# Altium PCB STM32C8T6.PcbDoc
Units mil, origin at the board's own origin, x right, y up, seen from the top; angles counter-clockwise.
Board outline 3865.24 x 3866.42 mil, 2 copper layers (Top Layer, Bottom Layer); 70 components, 62 nets, 378 pads, 47 vias.
Unrouted connection lines stored in the file: 3.
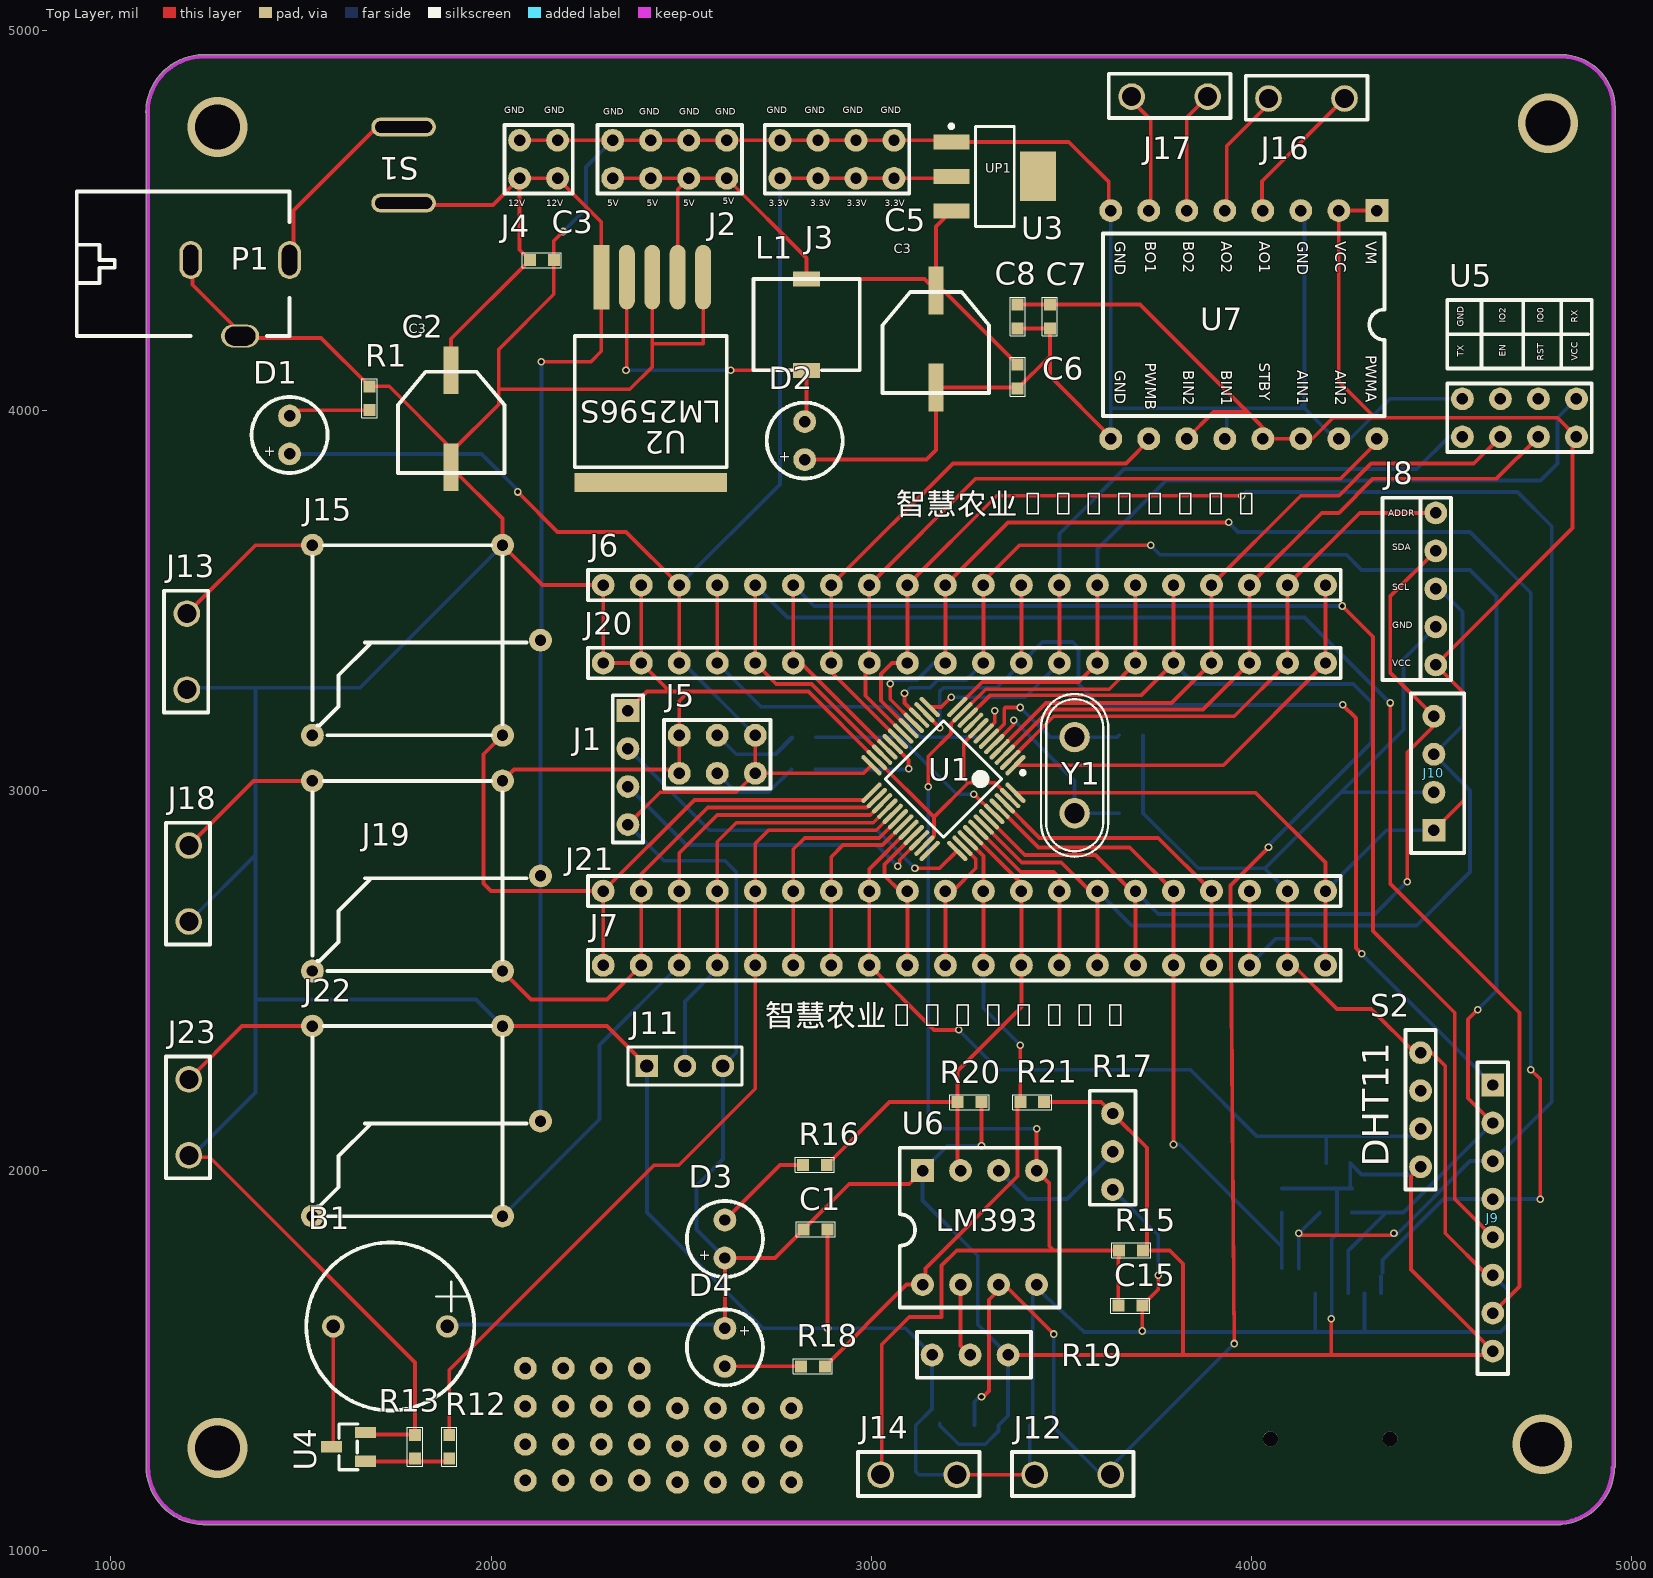
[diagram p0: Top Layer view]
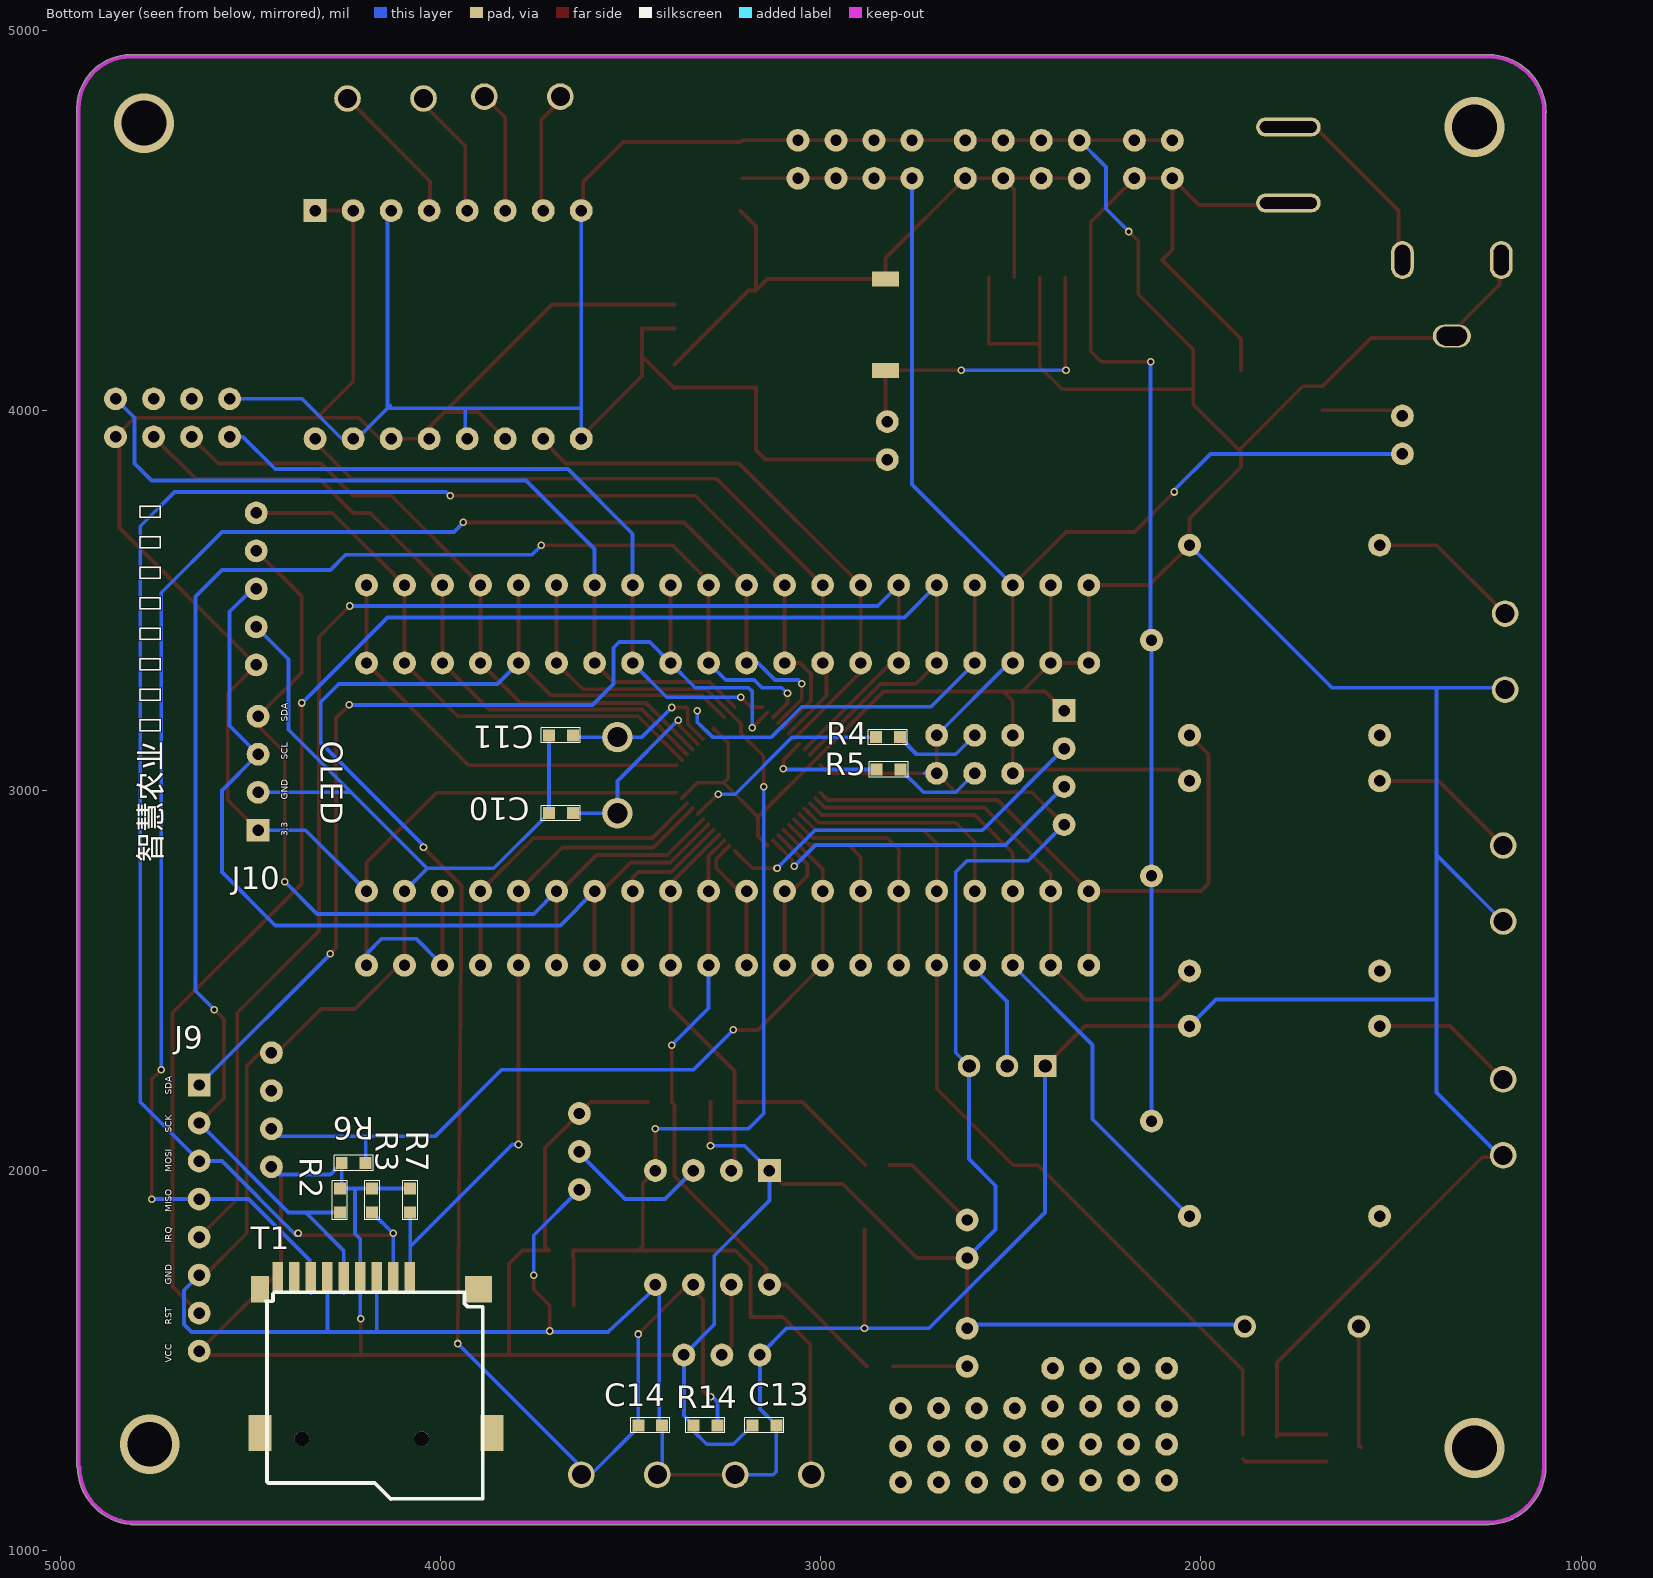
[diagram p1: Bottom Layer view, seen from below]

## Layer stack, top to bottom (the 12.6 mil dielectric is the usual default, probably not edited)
Top Solder: solder mask 0.4, Solder Resist, Dk 3.5
Top Layer: signal copper 1.4
Dielectric 1: dielectric 12.6, FR-4, Dk 4.8
Bottom Layer: signal copper 1.4
Bottom Solder: solder mask 0.4, Solder Resist, Dk 3.5

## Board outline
1093.29,1209.33 cw(c1098.09,1210.79) 1093.07,1210.79 1093.07,1212.39 cw(c1245.5,1221.67) 1092.81,1219.39 cw(c1097.82,1219.47) 1093.07,1221.08 1093.07,4781.92 cw(c1097.01,4785.02) 1092,4785.1 cw(c1244.68,4782.52) 1093.07,4800.77 1093.07,4801.91 cw(c1098.09,4801.91) 1093.48,4803.9 cw(c1244.68,4782.52) 1242.41,4935.21 cw(c1242.48,4930.2) 1243.37,4935.13 4814.56,4935.13 cw(c4814.56,4930.12) 4815.76,4934.98 cw(c4816.88,4930.1) 4816.97,4935.11 cw(c4814.56,4792.6) 4957.05,4795.95 cw(c4952.22,4794.6) 4957.24,4794.6 4957.24,1222.21 cw(c4952.22,1222.21) 4954.98,1218.02 cw(c4802.32,1221.48) 4815.96,1069.38 cw(c4814,1074) 4814,1068.98 4810.37,1068.98 cw(c4802.32,1221.48) 4804.59,1068.79 cw(c4804.52,1073.8) 4803.13,1068.98 1242,1068.98 cw(c1242,1074) 1241.42,1069.02 cw(c1245.5,1221.67)

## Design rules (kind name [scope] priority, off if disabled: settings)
Clearance [All] p1: gap=5
DiffPairsRouting [All] p1: maxlimit=5 minlimit=2 mostfreqgap=2 toplayer_minwidth=1 toplayer_maxwidth=5 toplayer_prefwidth=3 bottomlayer_minwidth=1 bottomlayer_maxwidth=5 bottomlayer_prefwidth=3 maxuncoupledlength=500
PolygonConnect [All] p1: connectstyle=Relief reliefconductorwidth=10 reliefentries=4 polygonreliefangle="90 Angle" airgapwidth=10
RoutingVias [All] p1: holewidth=5 width=10 viastyle="Through Hole" minholewidth=3 minwidth=5 maxholewidth=8 maxwidth=15
SolderMaskExpansion [All] p1: expansion=4
Width [All] p1: maxlimit=12 minlimit=5 preferedwidth=10 minimp=50.000000 maximp=50.000000 favimp=50.000000
28 further rules are at their usual default settings.

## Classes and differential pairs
component class Sheet2: C13 C14 C15 D3 D4 J8 J9 J10 J11 J12 J13 J14 J15 J16 J17 J18 J19 J22 J23 R14 R15 R16 R17 R18 R19 R20 R21 U5 U6 U7
component class Sheet1: B1 C1 C2 C3 C5 C6 C7 C8 C10 C11 D1 D2 J1 J2 J3 J4 J5 J6 J7 J20 J21 L1 P1 R1 R2 R3 R4 R5 R6 R7 R12 R13 S1 S2 T1 U1 U2 U3 U4 Y1

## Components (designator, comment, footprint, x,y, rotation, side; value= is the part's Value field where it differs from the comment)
B1 "BEEP" BEEP-9.5X5.5 1785,1590 r180 top
C1 "104" CAP_0603_FIRE 2885,1845 r180 top
C2 "220UF35V" CAP+_47UF_FIRE 1895,3995 r0 top
C3 "0.1UF" CAP_0603_FIRE 2165,4395 r180 top
C5 "220UF35V" CAP+_47UF_FIRE 3170,4205 r0 top
C6 "0.1UF" CAP_0603_FIRE 3385,4120 r270 top
C7 "22UF" CAP_0603_FIRE 3470,4215 r90 top
C8 "0.1UF" CAP_0603_FIRE 3385,4215 r90 top
C10 "20P" CAP_0603_FIRE 3715,2940 r180 bottom
C11 "20P" CAP_0603_FIRE 3715,3145 r180 bottom
C13 "104" CAP_0603_FIRE 3180,1330 r180 bottom
C14 "104" CAP_0603_FIRE 3417.01,1330 r0 bottom
C15 "104" CAP_0603_FIRE 3650,1645 r0 top
D1 "LED" LED_Z 1470,3885 r90 top
D2 "ES2D" LED_Z 2825,3870 r90 top
D3 "LED" LED_Z 2615,1770 r90 top
D4 "LED" LED_Z 2615,1585 r270 top
J1 "SWD" SWD 2360,3210 r0 top
J2 "5V" 5V 2320,4610 r90 top
J3 "3.3V" 3.3V 2760,4610 r90 top
J4 "12V" 12V 2075,4610 r90 top
J5 "BOOT" BOOT 2695,3145 r270 top
J6 "Hander_20" Hander_20 4195,3540 r270 top
J7 "Hander_20" Hander_20 4195,2540 r270 top
J8 "GY-302" GY 4485,3330 r180 top
J9 "RFID" RFID 4635,2225 r270 top
J10 "OLED" OLED 4480,2895 r90 top
J11 "HC-SR501" HDR1X3 2410,2275 r0 top
J12 "K1" port_2 3630,1200 r180 top
J13 "电磁阀" port_2 1200,3465 r270 top
J14 "Port" port_2 3225,1200 r180 top
J15 "relay" relay 1530,3145 r90 top
J16 "电机" port_2 4245,4820 r180 top
J17 "电机" port_2 3885,4825 r180 top
J18 "电磁阀" port_2 1205,2855 r270 top
J19 "relay" relay 1530,2525 r90 top
J20 "Hander_20" Hander_20 4195,3335 r270 top
J21 "Hander_20" Hander_20 4195,2735 r270 top
J22 "relay" relay 1530,1880 r90 top
J23 "电磁阀" port_2 1205,2240 r270 top
L1 "L" L 2830,4105 r180 top
P1 "Power" POWER 1310,4195 r90 top
R1 "1.5K" R_0603 1680,4000 r90 top
R2 "47K" R_0603 4265,1890 r90 bottom
R3 "47K" R_0603 4180,1890 r90 bottom
R4 "10K" R_0603 2855,3140 r180 bottom
R5 "10K" R_0603 2790,3055 r0 bottom
R6 "RES" R_0603 4260,2020 r180 bottom
R7 "47K" R_0603 4080,1890 r90 bottom
R12 "1K" R_0603 1890,1305 r270 top
R13 "10K" R_0603 1800,1305 r270 top
R14 "10K" R_0603 3272,1330 r0 bottom
R15 "10K" R_0603 3715,1790 r180 top
R16 "1k" R_0603 2820,2015 r0 top
R17 "103" RES_R 3635,1950 r180 top
R18 "1k" R_0603 2815,1485 r0 top
R19 "103" RES_R 3160,1515 r90 top
R20 "10K" R_0603 3290,2180 r180 top
R21 "10K" R_0603 3455,2180 r180 top
S1 "" SWITCH 1770,4745 r270 top
S2 "DHT11" DHT11 4445,2010 r90 top
T1 "TF" TF_CARD 4475,1310 r180 bottom
U1 "stm32c8t6" LQFP48_N 3190,3030 r225 top
U2 "LM2596" LM2596 2290,4350 r90 top
U3 "AMS1117" AMS-1117-3.3 3325,4615 r0 top
U4 "9014" SOT-23 1670,1235 r90 top
U5 "ESP8266" ESP8266 4555,3930 r90 top
U6 "LM393" LM393 3135,1700 r90 top
U7 "TB6612" TB6612 4330,4525 r270 top
Y1 "8MHZ" XTAL_socket 3535,3040 r90 top

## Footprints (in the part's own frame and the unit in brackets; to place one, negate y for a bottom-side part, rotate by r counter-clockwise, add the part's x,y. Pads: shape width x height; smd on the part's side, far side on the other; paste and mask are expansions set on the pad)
3.3V [mil]
  round 60 hole 30: 1(0,0) 2(0,-100) 3(0,-200) 4(0,-300) 5(100,-300) 6(100,-200) 7(100,-100) 8(100,0)
  silkscreen extent -40,-340 140,40
5V [mil]
  round 60 hole 30: 1(0,0) 2(0,-100) 3(0,-200) 4(0,-300) 5(100,0) 6(100,-100) 7(100,-200) 8(100,-300)
  silkscreen extent -40,-340 140,40
12V [mil]
  round 60 hole 30: 1(0,0) 2(0,-100) 3(100,0) 4(100,-100)
  silkscreen extent -40,-140 140,40
AMS-1117-3.3 [mm]
  rect 2.4x1 smd: 1(-2.9,2.3) 2(-2.9,0) 3(-2.9,-2.3)
  rect 2.4x3.3 smd: 4(2.9,0)
  silkscreen extent -3.02,-3.35 1.3,3.47
BEEP-9.5X5.5 [mm]
  round 1.5 hole 0.9: 1(-2.54,0) 2(5.08,0)
  silkscreen extent -4.34,-5.61 6.88,5.61
BOOT [mil]
  round 60 hole 30: 1(0,0) 2(0,-100) 3(0,-200) 4(100,-200) 5(100,-100) 6(100,0)
  silkscreen extent -40,-240 140,40
CAP+_47UF_FIRE [mm]
  rect 1x3.2 smd: 1(0,2.8) 2(0,-3.683)
  silkscreen extent -3.56,-4.06 3.56,2.7
CAP_0603_FIRE [mm]
  rect 0.8x0.8 smd: 1(0,0) 2(1.6,0)
  silkscreen extent -0.5,-0.5 2.1,0.5
DHT11 [mil]
  round 60 hole 30: 1(0,0) 2(100,0) 3(200,0) 4(300,0)
  silkscreen extent -60,-40 360,40
ESP8266 [mil]
  round 60 hole 30: 1(0,-300) 2(0,-200) 3(0,-100) 4(0,0) 5(100,-300) 6(100,-200) 7(100,-100) 8(100,0)
  silkscreen extent -40,-340 360,40
GY [mil]
  round 60 hole 30: 1(0,0) 2(0,-100) 3(0,-200) 4(0,-300) 5(0,-400)
  silkscreen extent -40,-440 140,40
Hander_20 [mil]
  round 60 hole 30: 1(0,0) 2(0,-100) 3(0,-200) 4(0,-300) 5(0,-400) 6(0,-500) 7(0,-600) 8(0,-700) 9(0,-800) 10(0,-900) 11(0,-1000) 12(0,-1100) 13(0,-1200) 14(0,-1300) 15(0,-1400) 16(0,-1500) 17(0,-1600) 18(0,-1700) 19(0,-1800) 20(0,-1900)
  silkscreen extent -40,-1940 40,40
HDR1X3 [mm] "Connector; Header; 3 Position"
  rect 1.5x1.5 hole 0.9: 1(0,0)
  round 1.5 hole 0.9: 2(2.54,0) 3(5.08,0)
  silkscreen extent -1.27,-1.27 6.35,1.27
L [mm]
  rect 1.8x1 all layers, no hole: 1(0,0) 2(0,-6.096)
  silkscreen extent -3.56,-6.1 3.56,0
LED_Z [mil]
  round 60 hole 30: 1(0,0) 2(100,0)
  silkscreen extent -50,-100 150,100
LM393 [mil]
  round 60 hole 30: 1(0,0) 2(0,-100) 3(0,-200) 4(0,-300) 5(300,-300) 6(300,-200) 7(300,-100)
  rect 60x60 hole 30: 8(300,0)
  silkscreen extent -60,-360 360,60
LM2596 [mil]
  rect 170x42 smd: 1(0,0)
  oval 170x42 smd: 2(0,-67) 3(0,-134) 4(0,-201) 5(0,-268)
  rect 50x400 smd: 6(-540,-130)
  silkscreen extent -500,-330 -155,70
LQFP48_N [mm]
  oval 1.8x0.3 smd: 1(-4.05,2.75) 2(-4.05,2.25) 3(-4.05,1.75) 4(-4.05,1.25) 5(-4.05,0.75) 6(-4.05,0.25) 7(-4.05,-0.25) 8(-4.05,-0.75) 9(-4.05,-1.25) 10(-4.05,-1.75) 11(-4.05,-2.25) 12(-4.05,-2.75) 25(4.05,-2.75) 26(4.05,-2.25) 27(4.05,-1.75) 28(4.05,-1.25) 29(4.05,-0.75) 30(4.05,-0.25) 31(4.05,0.25) 32(4.05,0.75) 33(4.05,1.25) 34(4.05,1.75) 35(4.05,2.25) 36(4.05,2.75)
  oval 0.3x1.8 smd: 13(-2.75,-4.05) 14(-2.25,-4.05) 15(-1.75,-4.05) 16(-1.25,-4.05) 17(-0.75,-4.05) 18(-0.25,-4.05) 19(0.25,-4.05) 20(0.75,-4.05) 21(1.25,-4.05) 22(1.75,-4.05) 23(2.25,-4.05) 24(2.75,-4.05) 37(2.75,4.05) 38(2.25,4.05) 39(1.75,4.05) 40(1.25,4.05) 41(0.75,4.05) 42(0.25,4.05) 43(-0.25,4.05) 44(-0.75,4.05) 45(-1.25,4.05) 46(-1.75,4.05) 47(-2.25,4.05) 48(-2.75,4.05)
  silkscreen extent -4.17,-2.75 2.75,3.57
OLED [mil]
  rect 60x60 hole 30: 1(0,0)
  round 60 hole 30: 2(100,0) 3(200,0) 4(300,0)
  silkscreen extent -60,-80 360,60
port_2 [mil]
  round 70 hole 50: 1(0,0) 2(200,0)
  silkscreen extent -60,-60 260,56
POWER [mil]
  oval 100x60 hole 40 slot 80 at 0 deg: 1(200,100) 3(200,-160)
  oval 60x100 hole 50 slot 80 at 90 deg: 2(0,-30)
  silkscreen extent 0,-160 380,400
R_0603 [mm]
  rect 0.8x0.8 smd: 1(0,0) 2(1.6,0)
  silkscreen extent -0.51,-0.51 2.11,0.51
relay [mil]
  round 60 hole 30: 1(0,0) 2(0,-500) 3(250,-600) 4(500,-500) 5(500,0)
  silkscreen extent 0,-564 500,0
RES_R [mil]
  round 60 hole 30: 1(0,0) 2(0,-200) 3(0,-100)
  silkscreen extent -60,-260 60,40
RFID [mil]
  rect 60x60 hole 30: 1(0,0)
  round 60 hole 30: 2(100,0) 3(200,0) 4(300,0) 5(400,0) 6(500,0) 7(600,0) 8(700,0)
  silkscreen extent -60,-40 760,40
SOT-23 [mil]
  rect 30x55 smd: 1(0,0) 2(76,0) 3(38,90)
  silkscreen extent -22,20 98,70
SWD [mil]
  rect 60x60 hole 30: 1(0,0)
  round 60 hole 30: 2(0,-100) 3(0,-200) 4(0,-300)
  silkscreen extent -40,-347 40,40
SWITCH [mil]
  oval 50x170 hole 30 slot 150 at 90 deg: 1(0,0) 2(200,0)
TB6612 [mil]
  rect 60x60 hole 30: 1(0,0)
  round 60 hole 30: 2(0,-100) 3(0,-200) 4(0,-300) 5(0,-400) 6(0,-500) 7(0,-600) 8(0,-700) 9(600,0) 10(600,-100) 11(600,-200) 12(600,-300) 13(600,-400) 14(600,-500) 15(600,-600) 16(600,-700)
  silkscreen extent 60,-720 540,20
TF_CARD [mm]
  rect 0.7x2.1 smd: 1(10,10.35) 2(8.9,10.35) 3(7.8,10.35) 4(6.7,10.35) 5(5.6,10.35) 6(4.5,10.35) 7(3.4,10.35) 8(2.3,10.35) 9(1.2,10.35)
  rect 1.2x1.778 smd: 10(0,9.6)
  rect 1.524x2.413 smd: 11(0,0) 12(15.5,0)
  rrect0% 1.778x1.778 smd: 13(14.6,9.6)
  round 1 hole 1: 14(10.8,-0.4) 15(2.8,-0.4)
  silkscreen extent 0.41,-4.42 14.88,9.4
XTAL_socket [mil]
  round 80 hole 53: 1(100,0) 2(-100,0)
  silkscreen extent -215,-89 214,89

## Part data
C1 C3 C6 C7 C8 C10 C11 C13 C14 C15: library part Capacitance
C2 C5: library part Capactiance+
D2: library part LED
J12 J13 J16 J17 J18 J23: library part port_2
R1 R2 R3 R4 R5 R7 R12 R13 R14 R15 R16 R18 R20 R21: library part RES
R17 R19: library part RES_R
S1: library part Switch
Y1: library part XTAL

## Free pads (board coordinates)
  round 60 hole 30: 0(2090,1185) 0(2090,1280) 0(2090,1380) 0(2090,1480) 0(2490,1180) 0(2490,1275) 0(2490,1375) 2(2190,1185) 2(2190,1280) 2(2190,1380) 2(2190,1480) 2(2590,1180) 2(2590,1275) 2(2590,1375) 3(2290,1185) 3(2290,1280) 3(2290,1380) 3(2290,1480) 3(2690,1180) 3(2690,1275) 3(2690,1375) 4(2390,1185) 4(2390,1280) 4(2390,1380) 4(2390,1480) 4(2790,1180) 4(2790,1275) 4(2790,1375)

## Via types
v1: diameter 20, hole 12, Top Layer to Bottom Layer, 43 vias
v2: diameter 157.48, hole 118.11, Top Layer to Bottom Layer, 4 vias

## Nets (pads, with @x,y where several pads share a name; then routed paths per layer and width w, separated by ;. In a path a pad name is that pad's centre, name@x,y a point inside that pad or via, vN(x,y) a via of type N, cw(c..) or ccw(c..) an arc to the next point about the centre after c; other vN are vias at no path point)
3.3V: B1.1 C1.2 C7.2 C8.2 C13.1 D1.1 D3.1 D4.1 J1.4 J3.1 J3.2 J3.3 J3.4 J5.1 J5.6 J6.18 J7.1 J7.3 J8.1 J9.8 J10.1 J11.3 J20.18 J21.1 J21.3 R2.2 R3.2 R6.1 R7.2 R14.2 R15.1 R17.2 R19.2 R20.1 R21.1 S2.1 T1.4 U1.9 U1.24 U1.36 U1.48 U3.2 U5.1 U6.8 U7.1 U7.2 U7.11 U7.12 U7.14 | length 17842.1
  Top Layer w10: v1(2070,3785) 2175,3680 2355,3680 J6.18 J20.18 ; J1.4 2445,2995 2645,2995 J5.6 ; D4.1 D3.1 2747.01,1770 C1.2 2942.01,1965 3100,1965 U6.8 ; J5.1 J5.6 ; J3.1 J3.2 J3.3 J3.4 U3.2@3205.83,4610 ; U1.24 2979.51,3045 J5.6 ; v1(3290,2065) R20.1 ; R19.2 3820,1515 ; U1.48 4011.19,2993.81 4195,2810 J21.1 J7.1 ; C8.2 C7.2 3707.01,4277.99 3990,3995 ; R21.1 3605,2180 R17.2 3725,2060 3725,1800 R15.1 3785,1790 3820,1755 3820,1515 ; U7.14 3900,3995 3990,3995 ; J7.3 J21.3 ; 4210,1520 v1(4210,1610) ; U7.1 U7.2 4230,4075 4325,3980 ; S2.1 4420,1985 4420,1740 J9.8 ; J10.1 4560,2975 4560,3255 J8.1 4845,3690 U5.1@4845,3930 ; J9.8@4625,1515 3820,1515 ; U5.1 4805,3980 4325,3980 ; 3990,3995 4060,3925 4160,3925 4215,3980 4325,3980
  Bottom Layer w10: D1.1 1975,3885 2067.5,3792.5 2067.5,3787.5 v1(2070,3785) ; B1.1@1870,1595 2605,1595 D4.1 ; J1.4 2455,2815 2615,2815 2645,2785 2645,2310 J11.3 2610,2030 2540,1960 2540,1845 D3.1 ; J20.18 2505,3335 J5.1 ; J6.18 2760,3805 J3.1@2760,4600 ; J5.6 2728,3045 ; C13.1@3180,1335 C13.1 3230,1280 3300,1280 3334.99,1314.99 R14.2 3360,1355.01 R19.2 3280,1595 3280,1776 3135,1921 U6.8 3200,2065 v1(3290,2065) ; J7.3 4065,2610 4155,2610 4195,2570 J7.1 ; R7.2 R3.2 4225,1952.99 ; J21.1 4355,2895 J10.1 ; v1@4211.22,1606.22 4211.22,1820 4225,1833.78 4225,1952.99 ; R2.2@4260,1957.99 R6.1 4290,1990 4425,1990 S2.1 ; R2.2 4225,1952.99 ; J9.8@4625,1515 J9.8
5V: C5.1 C6.1 J2.1 J2.2 J2.3 J2.4 L1.2 U2.4 U3.3 | length 1798.3
  Top Layer w10: J2.1 J2.2 J2.3 ; U2.4 2491,4581 J2.3 ; U3.3 3170,4483.62 C5.1 ; C6.1 3189.76,4315.24 C5.1 ; J2.3 J2.4 2830,4400 L1.2 3140.24,4345 C5.1
12V: C2.1 C3.2 J4.1 J4.2 J15.3 J19.3 J22.3 S1.2 U2.1 | length 3709.9
  Top Layer w10: S1.2@1770,4530 1780,4540 2005,4540 J4.1 ; C2.1 1895,4187.99 C3.2 2075,4422.01 J4.1 ; v1(2132.5,4127.5) 2262.5,4127.5 2290,4155 U2.1 2290,4495 J4.2 J4.1
  Bottom Layer w10: J22.3 J19.3 J15.3 2132.5,3397.5 v1(2132.5,4127.5)
BEEP: J7.16 J21.16 R12.1 U1.29 | length 2320.3
  Top Layer w10: R12.1 1890,1475 2428.75,2013.75 2493.75,2013.75 2695,2215 J7.16 J21.16 2695,2860 2730,2895 3013.24,2895 U1.29
BOOT0: R4.1 U1.44 | length 551.7
  Top Layer w10: v1(3270,2990) U1.44
  Bottom Layer w10: R4.1 3075,3140 3225,2990 v1(3270,2990)
BOOT1: R5.2 U1.20 | length 328.4
  Top Layer w10: U1.20 3098.24,3080 v1(3098.24,3056.76)
  Bottom Layer w10: R5.2 3096.48,3055 v1(3098.24,3056.76)
FIRE_IN: C15.1 J6.6 J14.2 J20.6 R15.2 U1.11 U6.5 | length 3741.7
  Top Layer w10: J14.2 3027.5,1202.5 3027.5,1542.5 3100,1615 3185,1615 3185,1750 3225,1790 R15.2 3652.01,1770.01 3650,1768 C15.1 ; v1(3150,3010) 3150,3090 3210,3150 3210,3175.27 U1.11 ; U1.11@3240.38,3205.38 3301.22,3266.22 3626.22,3266.22 J20.6 J6.6 ; v1(3435,2110) U6.5 3468,1967 3468,1802 3480,1790
  Bottom Layer w10: v1(3150,3010) 3150,2150 3190,2110 v1(3435,2110)
FIRE_IN2: R17.3 U6.6 | length 385.8
  Bottom Layer w10: U6.6 3410,1925 3515,1925 3635,2045 R17.3
FIRE_OUT: J7.9 J21.9 R16.2 R20.2 U1.40 U6.7 | length 1420.3
  Top Layer w10: R16.2 3047.99,2180 R20.2 ; U6.7 3227.01,2007.99 R20.2 ; U1.40 3395,2755.4 J21.9 J7.9 3395,2430 3227.01,2262.01 R20.2
GND: C1.1 C2.2 C3.1 C5.2 C6.2 C7.1 C8.1 C10.1 C11.1 C13.2 C14.1 C15.2 D2.1 J1.1 J2.5 J2.6 J2.7 J2.8 J3.5 J3.6 J3.7 J3.8 J4.3 J4.4 J5.3 J5.4 J6.19 J6.20 J7.2 J8.2 J9.6 J10.2 J11.1 J12.2 J13.2 J14.1 J15.4 J18.2 J19.4 J20.19 J20.20 J21.2 J22.4 J23.2 P1.1 P1.2 R1.2 R13.1 R17.1 R19.1 S2.4 T1.3 T1.6 U1.8 U1.23 U1.35 U1.47 U2.3 U2.5 U3.1 U4.2 U5.8 U6.4 U7.3 U7.8 U7.10 U7.13 U7.16 | length 24302.7
  Top Layer w10: P1.1@1215,4420 1215,4330 P1.2@1360,4185 ; J23.2@1220,2035 1260,2035 1800,1495 R13.1@1800,1300 ; P1.2@1350,4190 1552.99,4190 R1.2 1732.01,4062.99 C2.2@1895,3900 ; U4.2@1670,1306 R13.1@1800,1306 ; 2025,4055 2365,4055 2424,4114 2424,4175 ; J22.4 2305,2380 J11.1 ; J19.4 2060,3055 2485,3055 J5.4 J5.3 2495,3235 2520,3260 ; J4.3 J4.4 J2.5 J2.6 J2.7 J2.8 J3.8 J3.7 J3.6 J3.5 U3.1@3206.38,4710 ; v1(2190,4470) 2165,4445 C3.1 2165,4305 2020,4160 2020,4015 1895,3890 C2.2 2030,3715 J15.4 2135,3540 J6.20 J20.20 J20.19 ; J1.1 2410,3260 2470,3260 ; J6.19 J20.19 ; U2.3 2424,4175 ; U2.5 2558,4175 2424,4175 ; D2.1 3145,3870 3170,3895 C5.2 3385,4060 C6.2 3470,4142.01 C7.1 ; v1(2885,1585) C1.1 ; U1.35 3165,2879.73 3165,2929.73 ; U3.1 3519.45,4705.55 3625,4600 U7.8@3625,4540 ; J14.1@3212.01,1200 J14.1 J12.2 J12.2@3460,1200 ; U1.8@3281.87,3161.87 U1.8 3243.24,3125 3243.24,3032.03 3255.27,3020 ; U1.47 3325.27,3020 3255.27,3020 ; C8.1 C7.1 ; U7.16@3635,3925 3470,4090 C7.1 ; v1(3712.99,1577.99) C15.2 3755,1687.01 v1(3755,1725) ; J21.2 J7.2 4110,2540 4225,2425 4315,2425 4430,2310 4475,2310 4510,2275 4510,1835 4620,1725 J9.6 ; J20.19 2470,3260 ; 2470,3260 2520,3260 ; 2520,3260 2834.73,3260 U1.23 3165,2929.73 ; 3165,2929.73 3255.27,3020
  Bottom Layer w10: J13.2 1205,3270 1380,3270 ; J23.2@1205,2030 1380,2205 1380,2830 ; J18.2@1212.5,2662.5 1380,2830 ; 1385,2450 1960,2450 J22.4 ; J15.4 1655,3270 1380,3270 ; v1(2190,4470) 2250,4530 2250,4640 J2.5 ; J11.1 2410,1890 2715,1585 v1(2885,1585) 3090,1585 R19.1 3160,1372.99 C13.2 3117.01,1207.99 3125,1200 J14.1 ; J12.2 3417.01,1212.99 C14.1 3425,1337.99 3425,1700 3560,1575 4655,1575 4675,1595 4675,1685 J9.6 ; U7.16 3630,4005 ; U7.8 3630,4005 ; R17.1 3755,1830 v1(3755,1725) ; C11.1 C10.1 3860,2795 4035,2795 4035.27,2794.73 J21.2 ; U7.13@3935,3925 3935,4005 ; J21.2@4095,2745 J21.2 ; 4132.5,4012.5 4220,3925 4260,3925 4365,4030 U5.8 ; U7.3@4140,4505 4140,4005 3935,4005 ; 4167.91,1577.09 T1.3@4167.91,1677.48 ; 4297.83,1577.17 T1.6@4297.83,1677.48 ; J10.2 4235.55,2995 ; J8.2 4400,3345 4400,3159.45 4235.55,2995 ; 1380,2830 1380,3270 ; 3630,4005 3935,4005 ; J21.2 4035.28,2794.73 4235.55,2995
GY_INT: J7.4 J21.4 U1.46 | length 834.2
  Top Layer w10: U1.46 3442.44,2875 3755,2875 J21.4 J7.4
I2C_SCL: J7.7 J8.3 J10.3 J21.7 U1.42 | length 2492.4
  Top Layer w10: U1.42 3396.08,2810 3500,2810 3575,2735 J21.7 J7.7
  Bottom Layer w10: J21.7 3685,2645 4435,2645 4575,2785 4575,3000 J10.3 4555,3170 4555,3460 4555,3470 4495,3530 J8.3
I2C_SDA: J7.6 J8.4 J10.4 J21.6 U1.43 | length 2430.1
  Top Layer w10: U1.43 3403.92,2830 3590,2830 3685,2735 J21.6 J7.6 ; v1(4410,2760) 4410,3100 4480,3170 J10.4 4365,3310 4365,3510 J8.4
  Bottom Layer w10: J21.6 3755,2675 4325,2675 v1(4410,2760)
NetB1_2: B1.2 U4.3 | length 322.1
  Top Layer w10: U4.3 U4.3@1585,1278 ; U4.3@1585,1275 B1.2
NetD1_2: D1.2 R1.1 | length 216.2
  Top Layer w10: D1.2 1485,4000 R1.1
NetD2_2: D2.2 L1.1 U2.2 | length 855.1
  Top Layer w10: v1@2357,4107 U2.2 ; v1(2630,4105) L1.1 2830,3975 D2.2
  Bottom Layer w10: v1(2355,4105) v1(2630,4105)
NetD3_2: D3.2 R16.1 | length 265.1
  Top Layer w10: D3.2 2760,2015 R16.1
NetD4_2: D4.2 R18.1 | length 200
  Top Layer w10: D4.2@2610,1485 R18.1@2810,1485
NetJ5_2: J5.2 R4.2 | length 311.8
  Bottom Layer w10: J5.2@2605,3145 J5.2 2645,3095 2655,3095 2747.01,3095 ; 2747.01,3095 2750,3095 2792.01,3137.01 R4.2 2747.01,3095
NetJ5_5: J5.5 R5.1 | length 250.6
  Bottom Layer w10: J5.5@2605,3045 J5.5 2645,2995 2655,2995 2730,2995 R5.1
NetJ13_1: J13.1 J15.5 | length 404.6
  Top Layer w10: J13.1 1380,3645 J15.5
NetJ16_1: J16.1 U7.4 | length 389.7
  Top Layer w10: U7.4@4027.5,4527.5 4027.5,4602.5 J16.1@4250,4825
NetJ16_2: J16.2 U7.5 | length 340.6
  Top Layer w10: U7.5@3935,4525 3935,4695 4045,4805 J16.2
NetJ17_1: J17.1 U7.6 | length 322.8
  Top Layer w10: U7.6 3830,4770 J17.1
NetJ17_2: J17.2 U7.7 | length 320.7
  Top Layer w10: J17.2 3685,4815 3735,4765 U7.7@3735,4525
NetJ18_1: J18.1 J19.5 | length 395.4
  Top Layer w10: J18.1 1375,3025 J19.5
NetJ22_5: J22.5 J23.1 | length 383
  Top Layer w10: J23.1 1345,2380 J22.5
NetP1_3: P1.3 S1.1 | length 543.2
  Top Layer w10: P1.3@1480,4390 1480,4525 1695,4740 1785,4740 S1.1@1795,4730
NetR12_2: R12.2 R13.2 U4.1 | length 222.9
  Top Layer w10: U4.1 1882.99,1235 R12.2
NRST: J6.17 J20.17 U1.7 | length 1134.7
  Top Layer w10: J20.17 J6.17 ; U1.7 3325,3178.92 v1(3325,3210)
  Bottom Layer w10: J20.17 2710,3220 3050,3220 3130,3140 3285,3140 3325,3180 v1(3325,3210)
OSC_IN: C10.2 U1.5 Y1.2 | length 512.7
  Top Layer w10: U1.5 3375,3173.24 v1(3375,3185)
  Bottom Layer w10: v1(3375,3185) 3535,3025 Y1.2 C10.2
OSC_OUT: C11.2 U1.6 Y1.1 | length 434.2
  Top Layer w10: U1.6 3310.79,3135.79 3350,3175 3350,3215 3353.04,3218.04 v1(3391.96,3218.04)
  Bottom Layer w10: v1(3391.96,3218.04) 3470,3140 Y1.1 3647.01,3140 C11.2
PA0: C14.2 J6.5 J12.1 J20.5 R14.1 U1.10 U6.3 | length 4733.6
  Top Layer w10: U1.10 3312.56,3250 3710,3250 J20.5 J6.5 ; v1@3292.5,1402.5 3310,1420 3310,1660 3335,1685 U6.3 ; U6.3@3350,1700 v1(3480,1570) ; J12.1 J12.1@3640,1190 ; v1(3955,1545) 3945,2750 v1(4045,2850)
  Bottom Layer w10: R14.1 3272,1392 3285,1405 v1@3295,1405 ; C14.2 v1(3480,1570) ; C14.2@3485,1320 3605,1200 J12.1 ; J12.1@3607.5,1197.5 v1(3955,1545) ; J20.5 3850,3280 4268,3280 4315,3233 4315,3125 v1@4045,2855
  other v1: 3290,1405
PA2: J6.7 J20.7 U1.12 U5.5 | length 2210.6
  Top Layer w10: U1.12 3291.89,3285 3545,3285 J20.7 J6.7
  Bottom Layer w10: J6.7 3595,3635 3775,3815 4760,3815 4805,3860 4805,3980 U5.5
PA3: J6.8 J20.8 U1.13 U5.4 | length 1895.2
  Top Layer w10: U1.13 3184.3,3219.3 v1(3210,3245) ; J20.8 J6.8
  Bottom Layer w10: v1@3209.51,3245 v1(3210,3245) 3405,3245 J20.8 ; J6.8 3495,3675 3665,3845 4350,3845 4435,3845 4520,3930 U5.4
PA4: J6.9 J9.1 J20.9 U1.14 | length 2757.9
  Top Layer w10: U1.14 v1(3180,3165.27) ; J20.9 J6.9 ; v1(4240,3225) 4275,3190 4275,2585 v1(4290,2570)
  Bottom Layer w10: v1(3180,3165.27) 3180,3260 3190,3270 3330,3270 J20.9 3450,3390 3530,3390 3545,3375 3545,3280 3600,3225 v1(4240,3225) ; v1(4290,2570) J9.1
PA5: J6.10 J9.2 J20.10 R2.1 T1.5 U1.15 | length 4137.9
  Top Layer w10: v1(3087.44,3255) 3087.44,3230 U1.15 ; J20.10 J6.10 3295,3550 3390,3645 v1(3735,3645) ; v1(4595,2423) 4570,2398 4570,2190 J9.2
  Bottom Layer w10: v1(3087.44,3255) 3102.44,3270 3155,3270 3175,3290 3250,3290 J20.10 ; v1(3735,3645) 3760,3620 4250,3620 4290,3580 4575,3580 4645,3510 4645,2473 v1(4595,2423) ; T1.5@4254.53,1677.48 4254.53,1738 4255,1738.47 4255,1790 4350,1885 ; R2.1 4400,1890 J9.2
PA6: J6.11 J9.4 J20.11 T1.7 U1.16 | length 4349.9
  Top Layer w10: v1(3050,3280) 3050,3239.6 U1.16 ; J20.11 J6.11 3360,3705 v1(3940,3705) ; v1(4735,2265) 4760,2240 v1(4760,1925)
  Bottom Layer w10: v1(3050,3280) 3060,3290 3120,3290 3165,3335 J20.11 ; v1(3940,3705) 3965,3680 4575,3680 4735,3520 v1(4735,2265) ; T1.7@4341.14,1677.48 T1.7@4341.14,1721.14 ; T1.7@4345,1731.34 4345,1765 4505,1925 J9.4 v1(4760,1925)
PA7: J6.12 J9.3 J20.12 R3.1 T1.2 U1.17 | length 4802
  Top Layer w10: U1.17 3026,3235.76 3026,3306 3055,3335 J20.12 J6.12 3330,3775 v1(3975,3775) ; v1@4124.61,1830 4370,1830 v1(4375,1835)
  Bottom Layer w10: v1(3975,3775) 3985,3785 4700,3785 4790,3695 4790,2180 J9.3 4575,2025 4380,1830 4370,1830 v1(4375,1835) ; T1.2@4124.61,1742.48 v1(4124.61,1834.61) R3.1
PA9: J7.15 J21.15 U1.30 | length 613.1
  Top Layer w10: J7.15 J21.15 2795,2845 2825,2875 3021.08,2875 U1.30
PA10: J7.14 J21.14 U1.31 | length 509.5
  Top Layer w10: J7.14 J21.14 2895,2825 2926,2856 3029.92,2856 U1.31
PA11: J7.13 J21.13 R6.2 S2.2 U1.32 | length 2113.8
  Top Layer w10: U1.32 2995,2793.24 J21.13 J7.13 3165,2370 v1(3230,2370)
  Bottom Layer w10: v1(3230,2370) 3335,2265 3840,2265 4015,2090 4197.01,2090 ; R6.2 4197.01,2090 ; S2.2 4425,2090 4197.01,2090
PA12: J7.12 J21.12 U1.33 | length 410.7
  Top Layer w10: J7.12 J21.12 3075.4,2735 3035,2775.4 3035,2805.4 U1.33
PA15: J7.11 J21.11 U1.38 | length 373.9
  Top Layer w10: J7.11 J21.11 3215,2735 3275,2795 3275,2819.73 U1.38
PB0: J6.13 J20.13 U1.18 U7.9 | length 1945.9
  Top Layer w10: U1.18 2985,3248.92 2985,3335 J20.13 J6.13 3275,3820 4235,3820 U7.9@4340,3925
PB1: J6.14 J20.14 U1.19 U7.15 | length 1476.3
  Top Layer w10: U1.19 2895,3311.08 J20.14 J6.14 3215,3860 3670,3860 U7.15@3735,3925
PB3: J7.10 J21.10 R18.2 R21.2 U1.39 U6.1 | length 1678.2
  Top Layer w10: R18.2 3092.99,1700 U6.1 3142.5,1707.5 3142.5,1742.5 3385,1985 3385,2172.99 R21.2 v1(3392.01,2330) ; U1.39 3295,2827.56 J21.10 J7.10
  Bottom Layer w10: J7.10 3295,2427.01 v1(3392.01,2330)
PB5: J7.8 J21.8 U1.41 | length 495.5
  Top Layer w10: U1.41 3393.24,2785 3480,2785 3495,2770 J21.8 J7.8
PB8: J7.5 J21.5 R7.1 T1.1 U1.45 | length 1756.3
  Top Layer w10: U1.45 3439.6,2850 3680,2850 J21.5 J7.5 v1(3795,2068.57)
  Bottom Layer w10: v1(3795,2068.57) 3811.43,2068.57 4080,1800 ; T1.1@4080,1743.78 4080,1800 ; R7.1 4080,1800
PB10: J6.15 J9.5 J20.15 U1.21 | length 3837.3
  Top Layer w10: J6.15 J20.15 2815.4,3335 U1.21 ; v1(4239,3485) 4320,3404 4320,2630 4535,2415 4535,1925 J9.5
  Bottom Layer w10: J6.15 2850,3485 v1(4239,3485)
PB11: J6.16 J9.7 J20.16 U1.22 | length 4211.6
  Top Layer w10: J6.16 J20.16 2750,3280 2842.56,3280 U1.22 ; v1(4365,3230) 4365,2755 4705,2415 4705,1695 J9.7
  Bottom Layer w10: J6.16 2780,3455 4140,3455 v1(4365,3230)
PB12: J7.20 J15.2 J21.20 U1.25 | length 1741.9
  Top Layer w10: J15.2 1980,3095 1980,2755 2000,2735 J21.20 ; J7.20 J21.20 ; U1.25 2981.89,2975 2535,2975 J21.20
PB13: J7.19 J19.2 J21.19 U1.26 | length 1375.8
  Top Layer w10: J19.2 2105,2450 2305,2450 J7.19 J21.19 2395,2780 2570,2955 2989.73,2955 U1.26
PB14: J7.18 J21.18 J22.2 U1.27 | length 1745.4
  Top Layer w10: J7.18 J21.18 2495,2835 2595,2935 2997.56,2935 U1.27
  Bottom Layer w10: J22.2@2040,1880 J22.2 2285,2135 2285,2330 J7.18
PB15: J7.17 J11.2 J21.17 U1.28 | length 1108.7
  Top Layer w10: J7.17 J21.17 2595,2865 2645,2915 3005.4,2915 U1.28
  Bottom Layer w10: J11.2 2510,2445 2595,2530 J7.17
PC13: J6.2 J8.5 J20.2 U1.2 | length 1508.9
  Top Layer w10: U1.2 3480.27,3195 3955,3195 J20.2 J6.2 4285,3730 J8.5
PC14: J6.3 J20.3 U1.3 U5.2 | length 1869.9
  Top Layer w10: U1.3 3470,3212.56 3872.56,3212.56 J20.3 J6.3 4185,3730 4230,3730 4320,3820 4645,3820 U5.2
PC15: J6.4 J20.4 U1.4 U5.3 | length 1778
  Top Layer w10: U1.4 3459.6,3230 3790,3230 J20.4 J6.4 4130,3775 4230,3775 4315,3860 4585,3860 U5.3
SOIL_IN2: R19.3 U6.2 | length 195.4
  Top Layer w10: U6.2 3235,1540 R19.3
SWCLK: J1.2 U1.37 | length 1015.6
  Top Layer w10: v1(3115,2795) 3180,2795 3225.7,2840.7 U1.37
  Bottom Layer w10: J1.2 2575,2895 3015,2895 v1(3115,2795)
SWIO: J1.3 U1.34 | length 895.8
  Top Layer w10: v1(3070,2800) 3065,2800 3075,2810 3075,2817.56 U1.34
  Bottom Layer w10: J1.3 2514,2856 3014,2856 v1(3070,2800)
VBAT: J6.1 J20.1 U1.1 | length 1132
  Top Layer w10: U1.1 3926.19,3066.19 J20.1 J6.1
pads on no net: J15.1 J19.1 J22.1 S2.3 T1.8 T1.9 T1.10 T1.11 T1.12 T1.13 T1.14 T1.15 U2.6 U3.4 U5.6 U5.7
copper on no net:
  other v2: 1280,1270 4765,1280 1280,4745 4780,4755

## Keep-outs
Keep-Out Layer:
  lines w10: 1097.01,4785.02 cw(c1244.68,4782.52) 1242.48,4930.2 ; 1097.82,1219.47 ccw(c1245.5,1221.67) 1243,1074 ; 1098.09,1210.79 1098.09,4801.91 ; 1242,1074 4814,1074 ; 1242.48,4930.12 4814.56,4930.12 ; 4804.52,1073.8 ccw(c4802.32,1221.48) 4949.99,1218.98 ; 4816.88,4930.1 cw(c4814.56,4792.6) 4952.06,4794.65 ; 4952.22,1222.21 4952.22,4794.6

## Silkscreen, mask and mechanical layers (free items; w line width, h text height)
Top Overlay:
  text "智慧农业--flying" at 3065,3705 h100
  text "智慧农业--flying" at 2720,2360 h100
Bottom Overlay:
  text "SDA" at 4395,3180 h30 r270
  text "SCL" at 4395,3080 h30 r270
  text "GND" at 4395,2975 h30 r270
  text "3.3" at 4395,2880 h30 r270
  text "智慧农业--flying" at 4715,2810 h100 r270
